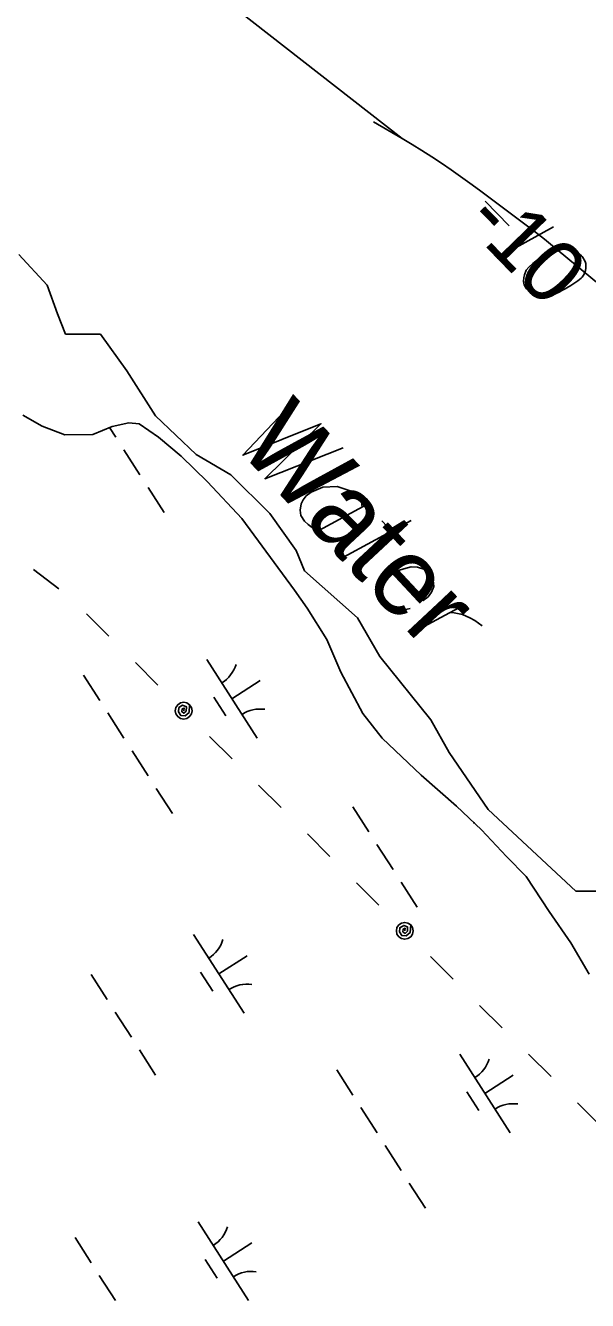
# Model space of a CAD drawing. Extents: x 3962991 to 3983549, y 181631 to 204078.
# Drawn here: x 3973990 to 3974291, y 192804 to 193487 of the extents above; entities that cross this region are included whole.
import ezdxf

# ---------------------------------------------------------------- set-up
doc = ezdxf.new("R2010")
doc.units = 0
for name, color, linetype in [('V-ANNO-MASK', 7, 'Continuous'), ('V-ANNO-MASK2', 7, 'Continuous'), ('V-RIVR-EDGE', 7, 'Continuous'), ('V-RIVR-IDEN', 7, 'Continuous'), ('V-RIVR-RANG', 7, 'Continuous'), ('V-TOPO-DPTH', 7, 'Continuous'), ('V-TOPO-MINR', 7, 'Continuous'), ('V-UTIL-LINE', 7, 'Continuous'), ('V-WETL-SWMP', 7, 'Continuous')]:
    doc.layers.add(name, color=color, linetype=linetype)

msp = doc.modelspace()

# ---------------------------------------------------------------- linework, layer by layer
at = {"layer": 'V-ANNO-MASK2'}
for p, q in [((3974236.52, 193392.89), (3974249.38, 193379.64)), ((3974273.07, 193379.11), (3974242.78, 193362.21)), ((3974173.09, 193230.41), (3974145.43, 193215.47)), ((3974158.73, 193201.2), (3974196.89, 193221.85)), ((3974181.21, 193221.7), (3974192.04, 193210.09)), ((3974196.17, 193161.04), (3974224.79, 193176.42))]:
    msp.add_line(p, q, dxfattribs=at)
for points in [[(3974288.5, 193363.21), (3974288.13, 193363.59), (3974286.84, 193364.54), (3974285.92, 193365.11), (3974285.18, 193365.49), (3974283.88, 193366.07), (3974282.21, 193366.66), (3974280.72, 193367.05), (3974279.05, 193367.27), (3974277.74, 193367.1), (3974276.24, 193366.75), (3974274.74, 193366.4), (3974273.06, 193365.86), (3974271.93, 193365.51), (3974270.43, 193364.78), (3974267.98, 193363.51), (3974264.59, 193361.32), (3974261.96, 193359.5), (3974259.87, 193357.48), (3974258.54, 193355.82), (3974257.57, 193353.41), (3974257.18, 193351.92), (3974256.96, 193349.87), (3974257.31, 193348), (3974257.67, 193347.25), (3974258.58, 193345.93), (3974259.5, 193344.98), (3974261.16, 193343.65), (3974262.82, 193342.7), (3974264.31, 193342.3), (3974266.54, 193341.89), (3974267.66, 193341.88), (3974269.15, 193341.86), (3974270.46, 193342.02), (3974271.4, 193342.2), (3974272.71, 193342.74), (3974273.27, 193342.91), (3974274.59, 193343.45), (3974276.09, 193344.18), (3974277.59, 193344.9), (3974278.53, 193345.45), (3974279.29, 193345.81), (3974280.23, 193346.35), (3974282.3, 193347.63), (3974283.43, 193348.36), (3974284.56, 193349.09), (3974286.07, 193350.19), (3974287.95, 193351.65), (3974288.52, 193352.2), (3974289.1, 193353.12), (3974289.67, 193354.05), (3974290.25, 193355.72), (3974290.46, 193357.02), (3974290.48, 193358.14), (3974290.31, 193359.45), (3974289.95, 193360.57), (3974289.59, 193361.33), (3974289.23, 193362.08), (3974288.5, 193363.21)], [(3974135.78, 193287.4), (3974106.86, 193256.83), (3974148.63, 193273.62), (3974118.59, 193244.25), (3974160.59, 193260.8)], [(3974170.71, 193229.09), (3974170.34, 193231.91), (3974166.5, 193236.02), (3974163.77, 193237.99), (3974157.29, 193240.09), (3974149.55, 193239.66), (3974143.38, 193237.06), (3974140.73, 193235.05), (3974139.02, 193233.01), (3974138.01, 193230.7), (3974137.42, 193227.45), (3974137.79, 193224.62), (3974139.79, 193221.51), (3974141.84, 193219.8), (3974143.88, 193218.09), (3974147.81, 193216.79)], [(3974188.92, 193194.52), (3974203.35, 193179.04), (3974206, 193181.06), (3974207.72, 193183.57), (3974209, 193186.57), (3974208.47, 193191.5), (3974206.45, 193194.14), (3974204.17, 193195.63), (3974200.23, 193196.94), (3974196.96, 193197.05), (3974192.95, 193196.02), (3974190.11, 193195.18), (3974185.1, 193192.32), (3974182.44, 193189.84), (3974180.49, 193187.56), (3974179.23, 193185.03), (3974179.27, 193179.65), (3974180.84, 193177.49), (3974182.88, 193175.78), (3974183.11, 193175.54), (3974187.49, 193173.75), (3974190.76, 193173.63), (3974192.65, 193174.04), (3974193.12, 193174.02), (3974196.42, 193174.84)], [(3974217.87, 193172.69), (3974219.97, 193172.38), (3974224.38, 193171.52), (3974228.3, 193169.75), (3974231.05, 193168.25), (3974234.94, 193165.54)]]:
    msp.add_lwpolyline(points, dxfattribs=at)
at = {"layer": 'V-RIVR-EDGE'}
msp.add_lwpolyline([(3973986.84, 193364.24), (3974002.13, 193347.86), (3974007.59, 193332.57), (3974011.96, 193321.65), (3974030.53, 193321.65), (3974044.72, 193301.99), (3974060.01, 193277.96), (3974081.86, 193257.21), (3974100.42, 193246.29), (3974121.17, 193225.54), (3974135.37, 193205.88), (3974139.74, 193194.96), (3974168.14, 193169.84), (3974180.15, 193149.08), (3974207.45, 193115.23), (3974217.28, 193097.75), (3974238.03, 193067.17), (3974285, 193023.49), (3974309.02, 193023.49)], dxfattribs=at)
at = {"layer": 'V-TOPO-DPTH'}
msp.add_lwpolyline([(3970915.42, 195982.24), (3974192.01, 193426.38), (3974197.36, 193423.2), (3974202.67, 193419.94), (3974207.91, 193416.57), (3974213.1, 193413.12), (3974218.23, 193409.59), (3974223.33, 193406.01), (3974228.38, 193402.37), (3974233.41, 193398.68), (3974258.51, 193380.02), (3974261.8, 193377.53), (3974265.08, 193375), (3974268.31, 193372.43), (3974271.51, 193369.82), (3974442.17, 193228.56)], dxfattribs=at)
at = {"layer": 'V-TOPO-MINR'}
msp.add_lwpolyline([(3974176.66, 193435.29), (3974192.01, 193426.38), (3974197.36, 193423.2), (3974202.67, 193419.94), (3974207.91, 193416.57), (3974213.1, 193413.12), (3974218.23, 193409.59), (3974223.33, 193406.01), (3974228.38, 193402.37), (3974233.41, 193398.68), (3974258.51, 193380.02), (3974261.8, 193377.53), (3974265.08, 193375), (3974268.31, 193372.43), (3974271.51, 193369.82), (3974442.17, 193228.56)], dxfattribs=at)
at = {"layer": 'V-UTIL-LINE'}
for points in [[(3973994.81, 193195.68), (3974008.3, 193185.34)], [(3974023.07, 193171.91), (3974035.12, 193159.91)], [(3974049.29, 193145.8), (3974061.33, 193133.8)], [(3974075.14, 193120.05), (3974075.4, 193121.47), (3974074.34, 193120.98), (3974074.13, 193119.62), (3974075.28, 193118.71), (3974076.53, 193119.85), (3974076.58, 193122.2), (3974074.58, 193122.94), (3974072.47, 193121.73), (3974072.36, 193119.45), (3974073.56, 193117.56), (3974075.97, 193117.34), (3974078.02, 193119.17), (3974078.32, 193123.24), (3974076.86, 193124.21), (3974075.13, 193124.55), (3974073.41, 193124.2), (3974071.95, 193123.23), (3974070.98, 193121.76), (3974070.64, 193120.04), (3974070.99, 193118.32), (3974071.97, 193116.86), (3974073.43, 193115.89), (3974075.15, 193115.55), (3974076.87, 193115.9), (3974078.33, 193116.88), (3974079.3, 193118.34), (3974079.64, 193120.06), (3974079.3, 193121.78), (3974078.32, 193123.24)], [(3974088.97, 193106.28), (3974101.01, 193094.28)], [(3974115.18, 193080.17), (3974127.23, 193068.17)], [(3974141.4, 193054.06), (3974153.44, 193042.06)], [(3974167.61, 193027.95), (3974179.66, 193015.95)], [(3974193.47, 193002.2), (3974193.72, 193003.62), (3974192.67, 193003.13), (3974192.46, 193001.77), (3974193.6, 193000.86), (3974194.86, 193002.01), (3974194.91, 193004.35), (3974192.91, 193005.09), (3974190.79, 193003.88), (3974190.69, 193001.6), (3974191.89, 192999.71), (3974194.29, 192999.49), (3974196.34, 193001.32), (3974196.64, 193005.39), (3974195.18, 193006.36), (3974193.46, 193006.7), (3974191.74, 193006.36), (3974190.28, 193005.38), (3974189.31, 193003.92), (3974188.97, 193002.19), (3974189.31, 193000.47), (3974190.29, 192999.01), (3974191.75, 192998.04), (3974193.48, 192997.7), (3974195.2, 192998.05), (3974196.65, 192999.03), (3974197.63, 193000.49), (3974197.97, 193002.21), (3974197.62, 193003.93), (3974196.64, 193005.39)], [(3974207.29, 192988.43), (3974219.34, 192976.43)], [(3974233.51, 192962.32), (3974245.55, 192950.32)], [(3974259.72, 192936.21), (3974271.77, 192924.21)], [(3974285.94, 192910.1), (3974297.99, 192898.1)]]:
    msp.add_lwpolyline(points, dxfattribs=at)
at = {"layer": 'V-WETL-SWMP'}
for p, q in [((3974035.46, 193271.67), (3974038.78, 193266.48)), ((3974043.1, 193259.75), (3974051.74, 193246.28)), ((3974056.05, 193239.54), (3974064.69, 193226.07)), ((3974087.47, 193147.52), (3974114.46, 193105.43)), ((3974021.59, 193139.05), (3974030.23, 193125.58)), ((3974100.96, 193126.48), (3974116.12, 193136.19)), ((3974091.23, 193127.36), (3974097.71, 193117.26)), ((3974034.54, 193118.84), (3974043.18, 193105.38)), ((3974047.5, 193098.64), (3974056.13, 193085.17)), ((3974060.45, 193078.44), (3974069.08, 193064.97)), ((3974165.59, 193068.68), (3974174.23, 193055.22)), ((3974230.43, 193060.19), (3974230.73, 193059.72)), ((3974178.54, 193048.48), (3974187.18, 193035.01)), ((3974191.5, 193028.28), (3974200.13, 193014.81)), ((3974080.46, 193000.21), (3974107.45, 192958.12)), ((3974093.96, 192979.16), (3974109.11, 192988.88)), ((3974025.56, 192978.91), (3974034.19, 192965.44)), ((3974084.22, 192980.05), (3974090.7, 192969.95)), ((3974038.51, 192958.71), (3974047.15, 192945.24)), ((3974051.46, 192938.5), (3974060.1, 192925.03)), ((3974222.91, 192936.26), (3974249.9, 192894.16)), ((3974157.03, 192927.78), (3974165.67, 192914.31)), ((3974236.41, 192915.21), (3974251.56, 192924.93)), ((3974226.67, 192916.1), (3974233.15, 192906)), ((3974169.99, 192907.58), (3974178.62, 192894.11)), ((3974182.94, 192887.37), (3974191.57, 192873.9)), ((3974195.89, 192867.17), (3974204.53, 192853.7)), ((3974082.88, 192846.48), (3974109.87, 192804.39)), ((3974017, 192838.01), (3974025.64, 192824.54)), ((3974096.37, 192825.44), (3974111.53, 192835.15)), ((3974086.64, 192826.32), (3974093.12, 192816.22)), ((3974029.95, 192817.8), (3974038.59, 192804.34))]:
    msp.add_line(p, q, dxfattribs=at)
msp.add_lwpolyline([(3973988.99, 193278.33), (3973999.33, 193272.41), (3974011.47, 193267.71), (3974026.58, 193267.89), (3974036.81, 193272.24), (3974045.85, 193274.16), (3974051.3, 193273.62), (3974061.65, 193266.48), (3974073.86, 193256.35), (3974087.92, 193242.61), (3974106.28, 193222.88), (3974134.53, 193184.53), (3974141.29, 193174.94), (3974151.76, 193158.14), (3974159.22, 193140.7), (3974170.96, 193118.47), (3974181.39, 193105.3), (3974202.17, 193085.59), (3974221.1, 193068.89), (3974234.54, 193056.35), (3974248.01, 193042), (3974258.41, 193031.25), (3974270.71, 193012.65), (3974282.39, 192995.87), (3974292.26, 192979.06)], dxfattribs=at)
for centre, start, end in [((3974086.26, 193149.86), 301.89187, 343.43553), ((3974116.07, 193103.35), 81.89186, 123.43552), ((3974079.25, 193002.54), 301.89187, 343.43553), ((3974109.06, 192956.04), 81.89186, 123.43552), ((3974221.7, 192938.59), 301.89187, 343.43553), ((3974251.51, 192892.09), 81.89186, 123.43552), ((3974081.67, 192848.82), 301.89187, 343.43553), ((3974111.48, 192802.31), 81.89186, 123.43552)]:
    msp.add_arc(centre, 17.62, start, end, dxfattribs=at)

# ---------------------------------------------------------------- texts
at = {"layer": 'V-ANNO-MASK'}
for s, height, rotation, p in [('-10', 33.5, 314.14786, (3974224.41, 193381.14)), ('Water', 42, 312.99603, (3974102.8, 193261.18))]:
    msp.add_text(s, height=height, rotation=rotation, dxfattribs=at).set_placement(p)
at = {"layer": 'V-RIVR-IDEN'}
msp.add_text('Water', height=42, rotation=312.99603, dxfattribs=at).set_placement((3974102.8, 193261.18))
at = {"layer": 'V-RIVR-RANG'}
msp.add_text('-10', height=33.5, rotation=314.14786, dxfattribs=at).set_placement((3974224.41, 193381.14))

doc.saveas('drawing.dxf')
